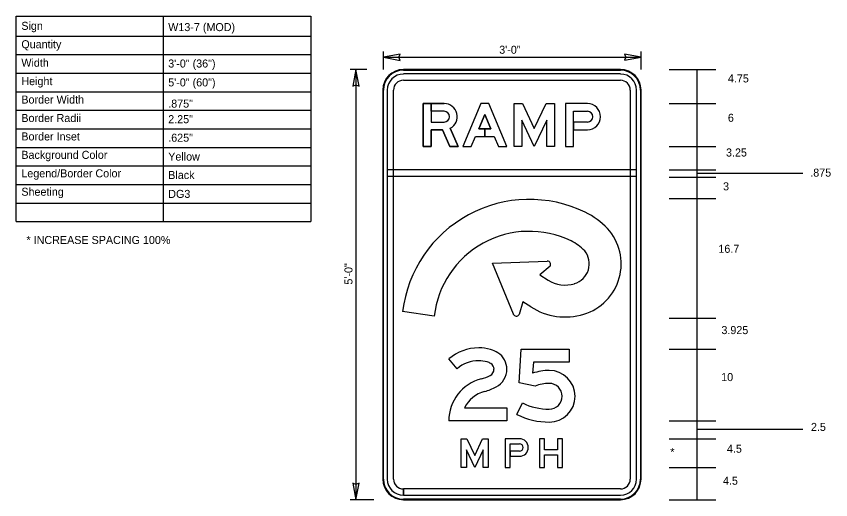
# Model space of a CAD drawing. Extents: x 582908 to 586041, y 1530940 to 1533040.
# Drawn here: x 583018 to 584437, y 1532197 to 1533040 of the extents above; entities that cross this region are included whole.
import ezdxf

# ---------------------------------------------------------------- set-up
doc = ezdxf.new("R2010")
doc.units = 0
for name, color, linetype in [('GSDims', 7, 'Continuous'), ('SheetLinesMisc2_dp', 7, 'Continuous'), ('SignPanel', 7, 'Continuous'), ('TextMisc', 7, 'Continuous'), ('TextNotes', 7, 'Continuous'), ('TextShtNo', 7, 'Continuous')]:
    doc.layers.add(name, color=color, linetype=linetype)

msp = doc.modelspace()

# ---------------------------------------------------------------- linework, layer by layer
at = {"layer": 'GSDims'}
for p, q in [((583657.9, 1532947), (583657.9, 1532978.4)), ((583686.9, 1532973.8), (583657.9, 1532968.4)), ((583657.9, 1532968.4), (584106.8, 1532968.4)), ((583657.9, 1532968.4), (583686.9, 1532962.8)), ((583684.7, 1532968.4), (583686.9, 1532973.8)), ((583686.9, 1532962.8), (583684.7, 1532968.4)), ((584106.8, 1532968.4), (584077.8, 1532974)), ((584077.8, 1532974), (584080, 1532968.4)), ((584080, 1532968.4), (584077.8, 1532963)), ((584077.8, 1532963), (584106.8, 1532968.4)), ((584106.8, 1532947), (584106.8, 1532978.4)), ((583629, 1532947), (583600, 1532947)), ((583610, 1532947), (583604.4, 1532918)), ((583610, 1532947), (583610, 1532197)), ((583615.4, 1532918), (583610, 1532947)), ((584155.6, 1532947), (584236.8, 1532947)), ((584204.3, 1532197), (584204.3, 1532947)), ((583604.4, 1532918), (583610, 1532920.2)), ((583610, 1532920.2), (583615.4, 1532918)), ((584155.6, 1532887.6), (584236.8, 1532887.6)), ((584155.6, 1532812.6), (584236.8, 1532812.6)), ((584155.6, 1532772), (584236.8, 1532772)), ((584155.6, 1532759.5), (584236.8, 1532759.5)), ((584204.3, 1532766.5), (584388.7, 1532766.5)), ((584155.6, 1532722), (584236.8, 1532722)), ((584155.6, 1532513.2), (584236.8, 1532513.2)), ((584155.6, 1532459.5), (584236.8, 1532459.5)), ((584155.6, 1532334.5), (584236.8, 1532334.5)), ((584204.3, 1532320.1), (584354, 1532320.1)), ((584343.4, 1532320.1), (584388.7, 1532320.1)), ((584155.6, 1532303.2), (584236.8, 1532303.2)), ((584155.6, 1532253.2), (584236.8, 1532253.2)), ((583610, 1532223.8), (583604.6, 1532226)), ((583604.6, 1532226), (583610, 1532197)), ((583610, 1532197), (583615.6, 1532226)), ((583615.6, 1532226), (583610, 1532223.8)), ((583641.4, 1532197), (583600, 1532197)), ((584155.6, 1532197), (584236.8, 1532197))]:
    msp.add_line(p, q, dxfattribs=at)
at = {"layer": 'SheetLinesMisc2_dp'}
for p, q in [((583018.3, 1532681.8), (583018.3, 1533039.8)), ((583018.3, 1533039.8), (583531.6, 1533039.8)), ((583274.2, 1533039.8), (583274.2, 1532681.8)), ((583531.6, 1533039.8), (583531.6, 1532681.8)), ((583018.3, 1533005.2), (583531.6, 1533005.2)), ((583018.3, 1532972.9), (583531.6, 1532972.9)), ((583018.3, 1532940.5), (583531.6, 1532940.5)), ((583018.3, 1532908.2), (583531.6, 1532908.2)), ((583018.3, 1532875.8), (583531.6, 1532875.8)), ((583018.3, 1532843.5), (583531.6, 1532843.5)), ((583018.3, 1532811.1), (583531.6, 1532811.1)), ((583018.3, 1532778.8), (583531.6, 1532778.8)), ((583018.3, 1532746.5), (583531.6, 1532746.5)), ((583018.3, 1532714.1), (583531.6, 1532714.1)), ((583018.3, 1532681.8), (583531.6, 1532681.8))]:
    msp.add_line(p, q, dxfattribs=at)
at = {"layer": 'SignPanel'}
for p, q in [((584070.9, 1532947), (583692.7, 1532947)), ((583692.7, 1532945.9), (584070.9, 1532945.9)), ((584070.9, 1532939.2), (583692.7, 1532939.2)), ((583692.7, 1532928.2), (584070.9, 1532928.2)), ((583656.8, 1532911), (583656.8, 1532232.9)), ((583657.9, 1532232.9), (583657.9, 1532911)), ((583664.6, 1532911), (583664.6, 1532232.9)), ((583675.6, 1532232.9), (583675.6, 1532911)), ((584088.1, 1532911), (584088.1, 1532232.9)), ((584099, 1532232.9), (584099, 1532911)), ((584105.7, 1532911), (584105.7, 1532232.9)), ((584106.8, 1532232.9), (584106.8, 1532911)), ((583988.9, 1532874.1), (584013.3, 1532874.1)), ((583988.9, 1532874.1), (584013.3, 1532874.1)), ((583988.9, 1532874.1), (584013.3, 1532874.1)), ((583988.9, 1532841.9), (584013.3, 1532841.9)), ((584099, 1532772), (583664.6, 1532772)), ((583664.6, 1532772), (583664.6, 1532761)), ((584099, 1532772), (583664.6, 1532772)), ((583664.6, 1532772), (583664.6, 1532761)), ((584099, 1532772), (583664.6, 1532772)), ((583664.6, 1532772), (583664.6, 1532761)), ((584099, 1532761), (584099, 1532772)), ((584099, 1532761), (584099, 1532772)), ((584099, 1532761), (584099, 1532772)), ((583664.6, 1532761), (584099, 1532761)), ((583664.6, 1532761), (584099, 1532761)), ((583664.6, 1532761), (584099, 1532761)), ((583847.9, 1532609.1), (583943.5, 1532613)), ((583884.3, 1532520.5), (583847.9, 1532609.1)), ((583948.3, 1532604.1), (583930.7, 1532589)), ((583930.7, 1532589), (583944.7, 1532580)), ((583900.7, 1532542.2), (583894.3, 1532519.9)), ((583914.7, 1532533.2), (583900.7, 1532542.2)), ((583746.4, 1532516.9), (583691.4, 1532525.3)), ((583890.5, 1532345.4), (583900.5, 1532365.6)), ((583890.5, 1532345.4), (583900.5, 1532365.6)), ((583890.5, 1532345.4), (583900.5, 1532365.6)), ((583878.9, 1532294.2), (583895.1, 1532294.2)), ((583878.9, 1532294.2), (583895.1, 1532294.2)), ((583878.9, 1532294.2), (583895.1, 1532294.2)), ((583878.9, 1532272.7), (583895.1, 1532272.7)), ((583692.7, 1532204.8), (583692.7, 1532215.7)), ((584070.9, 1532215.7), (583692.9, 1532215.7)), ((583692.9, 1532215.7), (583692.9, 1532204.8)), ((583692.9, 1532204.8), (584070.9, 1532204.8)), ((583692.7, 1532197), (583692.7, 1532198.1)), ((584070.9, 1532198.1), (583692.8, 1532198.1)), ((583692.8, 1532198.1), (583692.8, 1532197)), ((583692.8, 1532197), (584070.9, 1532197))]:
    msp.add_line(p, q, dxfattribs=at)
for points in [[(583763.7, 1532887.6), (583727.4, 1532887.6), (583727.4, 1532812.6), (583740.9, 1532812.6), (583740.9, 1532841.9), (583760.8, 1532841.9), (583773.5, 1532812.6), (583788.2, 1532812.6), (583774.4, 1532844.5)], [(583774.4, 1532844.5), (583788.2, 1532812.6), (583773.5, 1532812.6), (583760.8, 1532841.9), (583740.9, 1532841.9), (583740.9, 1532812.6), (583727.4, 1532812.6), (583727.4, 1532887.6), (583740.9, 1532887.6), (583740.9, 1532855.4), (583763.7, 1532855.4)], [(583774.4, 1532844.5), (583788.2, 1532812.6), (583773.5, 1532812.6), (583760.8, 1532841.9), (583740.9, 1532841.9), (583740.9, 1532812.6), (583727.4, 1532812.6), (583727.4, 1532887.6), (583740.9, 1532887.6), (583740.9, 1532855.4), (583763.7, 1532855.4)], [(583740.9, 1532874.1), (583740.9, 1532887.6), (583763.7, 1532887.6)], [(583740.9, 1532874.1), (583740.9, 1532887.6), (583763.7, 1532887.6)], [(584013.3, 1532887.6), (583975.4, 1532887.6), (583975.4, 1532812.6), (583988.9, 1532812.6), (583988.9, 1532841.9)], [(584013.3, 1532887.6), (583975.4, 1532887.6), (583975.4, 1532812.6), (583988.9, 1532812.6), (583988.9, 1532874.1)], [(584013.3, 1532887.6), (583975.4, 1532887.6), (583975.4, 1532812.6), (583988.9, 1532812.6), (583988.9, 1532874.1)], [(583763.7, 1532874.1), (583740.9, 1532874.1), (583740.9, 1532855.4), (583763.7, 1532855.4)], [(583763.7, 1532874.1), (583740.9, 1532874.1)], [(583763.7, 1532874.1), (583740.9, 1532874.1)], [(584013.3, 1532855.4), (583988.9, 1532855.4), (583988.9, 1532874.1)], [(584013.3, 1532855.4), (583988.9, 1532855.4), (583988.9, 1532841.9), (584013.3, 1532841.9)], [(584013.3, 1532855.4), (583988.9, 1532855.4), (583988.9, 1532841.9), (584013.3, 1532841.9)], [(583922.1, 1532395.1), (583894.3, 1532400.7), (583898, 1532459.5), (583981.8, 1532459.5), (583981.8, 1532437), (583919.2, 1532437), (583917.9, 1532417.5)], [(583922.1, 1532395.1), (583894.3, 1532400.7), (583898, 1532459.5), (583981.8, 1532459.5), (583981.8, 1532437), (583919.2, 1532437), (583917.9, 1532417.5)], [(583922.1, 1532395.1), (583894.3, 1532400.7), (583898, 1532459.5), (583981.8, 1532459.5), (583981.8, 1532437), (583919.2, 1532437), (583917.9, 1532417.5)], [(583786.4, 1532425.4), (583771.8, 1532442.5)], [(583786.4, 1532425.4), (583771.8, 1532442.5)], [(583786.4, 1532425.4), (583771.8, 1532442.5)], [(583799.3, 1532357), (583873, 1532357), (583873, 1532334.5), (583771.8, 1532334.5)], [(583799.3, 1532357), (583873, 1532357), (583873, 1532334.5), (583771.8, 1532334.5)], [(583799.3, 1532357), (583873, 1532357), (583873, 1532334.5), (583771.8, 1532334.5)], [(583895.1, 1532303.2), (583869.9, 1532303.2), (583869.9, 1532253.2), (583878.9, 1532253.2), (583878.9, 1532272.7)], [(583895.1, 1532303.2), (583869.9, 1532303.2), (583869.9, 1532253.2), (583878.9, 1532253.2), (583878.9, 1532294.2)], [(583895.1, 1532303.2), (583869.9, 1532303.2), (583869.9, 1532253.2), (583878.9, 1532253.2), (583878.9, 1532294.2)], [(583895.1, 1532281.7), (583878.9, 1532281.7), (583878.9, 1532294.2)], [(583895.1, 1532281.7), (583878.9, 1532281.7), (583878.9, 1532272.7), (583895.1, 1532272.7)], [(583895.1, 1532281.7), (583878.9, 1532281.7), (583878.9, 1532272.7), (583895.1, 1532272.7)]]:
    msp.add_lwpolyline(points, dxfattribs=at)
for points in [[(583818.4, 1532830.2), (583850.8, 1532830.2), (583858.2, 1532812.6), (583872.9, 1532812.6), (583841.4, 1532887.6), (583827.9, 1532887.6), (583796.4, 1532812.6), (583811, 1532812.6)], [(583845.2, 1532843.7), (583834.6, 1532843.7), (583834.6, 1532830.2), (583850.8, 1532830.2), (583858.2, 1532812.6), (583872.9, 1532812.6), (583841.4, 1532887.6), (583827.9, 1532887.6), (583796.4, 1532812.6), (583811, 1532812.6), (583818.4, 1532830.2), (583834.6, 1532830.2), (583834.6, 1532843.7), (583824.1, 1532843.7), (583834.6, 1532868.8)], [(583845.2, 1532843.7), (583834.6, 1532843.7), (583834.6, 1532830.2), (583850.8, 1532830.2), (583858.2, 1532812.6), (583872.9, 1532812.6), (583841.4, 1532887.6), (583827.9, 1532887.6), (583796.4, 1532812.6), (583811, 1532812.6), (583818.4, 1532830.2), (583834.6, 1532830.2), (583834.6, 1532843.7), (583824.1, 1532843.7), (583834.6, 1532868.8)], [(583920.8, 1532844.1), (583941.5, 1532887.6), (583956, 1532887.6), (583956, 1532812.6), (583942.5, 1532812.6), (583942.5, 1532858.4), (583920.8, 1532812.6), (583899, 1532858.4), (583899, 1532812.6), (583885.5, 1532812.6), (583885.5, 1532887.6), (583900.1, 1532887.6)], [(583920.8, 1532844.1), (583941.5, 1532887.6), (583956, 1532887.6), (583956, 1532812.6), (583942.5, 1532812.6), (583942.5, 1532858.4), (583920.8, 1532812.6), (583899, 1532858.4), (583899, 1532812.6), (583885.5, 1532812.6), (583885.5, 1532887.6), (583900.1, 1532887.6)], [(583920.8, 1532844.1), (583941.5, 1532887.6), (583956, 1532887.6), (583956, 1532812.6), (583942.5, 1532812.6), (583942.5, 1532858.4), (583920.8, 1532812.6), (583899, 1532858.4), (583899, 1532812.6), (583885.5, 1532812.6), (583885.5, 1532887.6), (583900.1, 1532887.6)], [(583845.2, 1532843.7), (583834.6, 1532868.8), (583824.1, 1532843.7)], [(583817, 1532274.2), (583830.8, 1532303.2), (583840.5, 1532303.2), (583840.5, 1532253.2), (583831.5, 1532253.2), (583831.5, 1532283.7), (583817, 1532253.2), (583802.5, 1532283.7), (583802.5, 1532253.2), (583793.5, 1532253.2), (583793.5, 1532303.2), (583803.2, 1532303.2)], [(583817, 1532274.2), (583830.8, 1532303.2), (583840.5, 1532303.2), (583840.5, 1532253.2), (583831.5, 1532253.2), (583831.5, 1532283.7), (583817, 1532253.2), (583802.5, 1532283.7), (583802.5, 1532253.2), (583793.5, 1532253.2), (583793.5, 1532303.2), (583803.2, 1532303.2)], [(583817, 1532274.2), (583830.8, 1532303.2), (583840.5, 1532303.2), (583840.5, 1532253.2), (583831.5, 1532253.2), (583831.5, 1532283.7), (583817, 1532253.2), (583802.5, 1532283.7), (583802.5, 1532253.2), (583793.5, 1532253.2), (583793.5, 1532303.2), (583803.2, 1532303.2)], [(583961.1, 1532284.2), (583938.6, 1532284.2), (583938.6, 1532303.2), (583929.6, 1532303.2), (583929.6, 1532253.2), (583938.6, 1532253.2), (583938.6, 1532275.2), (583961.1, 1532275.2), (583961.1, 1532253.2), (583970.1, 1532253.2), (583970.1, 1532303.2), (583961.1, 1532303.2)], [(583961.1, 1532284.2), (583938.6, 1532284.2), (583938.6, 1532303.2), (583929.6, 1532303.2), (583929.6, 1532253.2), (583938.6, 1532253.2), (583938.6, 1532275.2), (583961.1, 1532275.2), (583961.1, 1532253.2), (583970.1, 1532253.2), (583970.1, 1532303.2), (583961.1, 1532303.2)], [(583961.1, 1532284.2), (583938.6, 1532284.2), (583938.6, 1532303.2), (583929.6, 1532303.2), (583929.6, 1532253.2), (583938.6, 1532253.2), (583938.6, 1532275.2), (583961.1, 1532275.2), (583961.1, 1532253.2), (583970.1, 1532253.2), (583970.1, 1532303.2), (583961.1, 1532303.2)]]:
    msp.add_lwpolyline(points, close=True, dxfattribs=at)
for centre, radius, start, end in [((583692.7, 1532911), 35.9, 90, 180), ((583692.7, 1532911), 34.8, 90, 180), ((583692.7, 1532911), 28.1, 90, 180), ((584070.9, 1532911), 35.9, 0, 90), ((584070.9, 1532911), 34.8, 0, 90), ((584070.9, 1532911), 28.1, 0, 90), ((583692.7, 1532911), 17.2, 90, 180), ((584070.9, 1532911), 17.2, 0, 90), ((583912.1, 1532498.2), 222.3, 64.0026, 173.0199), ((583945.4, 1532569.1), 144.1, 44.3092, 63.5547), ((583980.5, 1532608.2), 91.7, 286.8096, 42.1395), ((583912.1, 1532498.2), 166.7, 64.0026, 173.5767), ((583945.4, 1532569.1), 88.4, 44.3092, 63.5547), ((583980.5, 1532608.2), 36.1, 286.8096, 38.803), ((583943.7, 1532607.4), 5.6, 324.4393, 92.3246), ((583974.7, 1532626.8), 55.6, 237.3246, 286.8677), ((583974.7, 1532626.8), 111.2, 237.3246, 286.8677), ((583889.4, 1532522.6), 5.56, 202.3246, 331.1534), ((583692.7, 1532232.9), 35.9, 180, 270), ((583692.7, 1532232.9), 34.8, 180, 270), ((583692.7, 1532232.9), 28.1, 180, 270), ((583692.7, 1532232.9), 17.2, 180, 270), ((584070.9, 1532232.9), 28.1, 270, 0), ((584070.9, 1532232.9), 17.2, 270, 0), ((584070.9, 1532232.9), 35.9, 270, 0), ((584070.9, 1532232.9), 34.8, 270, 0)]:
    msp.add_arc(centre, radius, start, end, dxfattribs=at)
for centre, major_axis, start_param, end_param in [((583763.7, 1532864.7), (0, 22.9), 3.62744, 6.283185), ((583763.7, 1532864.7), (0, 22.9), 3.62744, 6.283185), ((583763.7, 1532864.7), (0, 22.9), 3.62744, 6.283185), ((584013.3, 1532864.7), (0, 22.9), 3.141593, 6.283185), ((584013.3, 1532864.7), (0, 22.9), 3.141593, 6.283185), ((584013.3, 1532864.7), (0, 22.9), 3.141593, 6.283185), ((583763.7, 1532864.7), (0, 9.37), 3.141593, 6.283185), ((583763.7, 1532864.7), (0, 9.37), 3.141593, 6.283185), ((583763.7, 1532864.7), (0, 9.37), 3.141593, 6.283185), ((584013.3, 1532864.7), (0, 9.37), 3.141593, 6.283185), ((584013.3, 1532864.7), (0, 9.37), 3.141593, 6.283185), ((584013.3, 1532864.7), (0, 9.37), 3.141593, 6.283185), ((583824, 1532381), (0, 80.7), 0, 0.70376), ((583824, 1532381), (0, 80.7), 0, 0.70376), ((583824, 1532381), (0, 80.7), 0, 0.70376), ((583824, 1532382.7), (0, 79), 6.02311, 6.283185), ((583824, 1532382.7), (0, 79), 6.02311, 6.283185), ((583824, 1532382.7), (0, 79), 6.02311, 6.283185), ((583832.5, 1532414.7), (0, 45.8), 5.706931, 6.02311), ((583832.5, 1532414.7), (0, 45.8), 5.706931, 6.02311), ((583832.5, 1532414.7), (0, 45.8), 5.706931, 6.02311), ((583838.9, 1532424.5), (0, 34.2), 4.712389, 5.706931), ((583838.9, 1532424.5), (0, 34.2), 4.712389, 5.706931), ((583838.9, 1532424.5), (0, 34.2), 4.712389, 5.706931), ((583824, 1532381), (0, 58.2), 0, 0.70376), ((583824, 1532381), (0, 58.2), 0, 0.70376), ((583824, 1532381), (0, 58.2), 0, 0.70376), ((583824, 1532382.7), (0, 56.5), 6.02311, 6.283185), ((583824, 1532382.7), (0, 56.5), 6.02311, 6.283185), ((583824, 1532382.7), (0, 56.5), 6.02311, 6.283185), ((583832.5, 1532414.7), (0, 23.3), 5.706931, 6.02311), ((583832.5, 1532414.7), (0, 23.3), 5.706931, 6.02311), ((583832.5, 1532414.7), (0, 23.3), 5.706931, 6.02311), ((583838.9, 1532424.5), (0, 11.7), 4.712389, 5.706931), ((583838.9, 1532424.5), (0, 11.7), 4.712389, 5.706931), ((583838.9, 1532424.5), (0, 11.7), 4.712389, 5.706931), ((583838.1, 1532424.5), (0, 12.4), 3.626327, 4.712389), ((583838.1, 1532424.5), (0, 12.4), 3.626327, 4.712389), ((583838.1, 1532424.5), (0, 12.4), 3.626327, 4.712389), ((583838.1, 1532424.5), (0, 34.9), 3.626327, 4.712389), ((583838.1, 1532424.5), (0, 34.9), 3.626327, 4.712389), ((583838.1, 1532424.5), (0, 34.9), 3.626327, 4.712389), ((583946.8, 1532332.3), (0, 90), 0, 0.326688), ((583946.8, 1532332.3), (0, 90), 0, 0.326688), ((583946.8, 1532332.3), (0, 90), 0, 0.326688), ((583946.8, 1532377.3), (0, 45), 3.141593, 6.283185), ((583946.8, 1532377.3), (0, 45), 3.141593, 6.283185), ((583946.8, 1532377.3), (0, 45), 3.141593, 6.283185), ((583847.3, 1532334.5), (0, 75.5), 0.25053, 1.570796), ((583847.3, 1532334.5), (0, 75.5), 0.25053, 1.570796), ((583847.3, 1532334.5), (0, 75.5), 0.25053, 1.570796), ((583811.1, 1532475.8), (0, 70.4), 3.392123, 3.626327), ((583811.1, 1532475.8), (0, 70.4), 3.392123, 3.626327), ((583811.1, 1532475.8), (0, 70.4), 3.392123, 3.626327), ((583946.8, 1532332.3), (0, 67.5), 0, 0.374869), ((583946.8, 1532332.3), (0, 67.5), 0, 0.374869), ((583946.8, 1532332.3), (0, 67.5), 0, 0.374869), ((583946.8, 1532377.3), (0, 22.5), 3.141593, 6.283185), ((583946.8, 1532377.3), (0, 22.5), 3.141593, 6.283185), ((583946.8, 1532377.3), (0, 22.5), 3.141593, 6.283185), ((583847.3, 1532334.5), (0, 53), 0.25053, 1.132058), ((583847.3, 1532334.5), (0, 53), 0.25053, 1.132058), ((583847.3, 1532334.5), (0, 53), 0.25053, 1.132058), ((583811.1, 1532475.8), (0, 92.9), 3.392123, 3.626327), ((583811.1, 1532475.8), (0, 92.9), 3.392123, 3.626327), ((583811.1, 1532475.8), (0, 92.9), 3.392123, 3.626327), ((583946.8, 1532459.2), (0, 104.4), 2.68226, 3.141593), ((583946.8, 1532459.2), (0, 104.4), 2.68226, 3.141593), ((583946.8, 1532459.2), (0, 104.4), 2.68226, 3.141593), ((583946.8, 1532459.2), (0, 126.9), 2.68226, 3.141593), ((583946.8, 1532459.2), (0, 126.9), 2.68226, 3.141593), ((583946.8, 1532459.2), (0, 126.9), 2.68226, 3.141593), ((583895.1, 1532288), (0, 15.2), 3.141593, 6.283185), ((583895.1, 1532288), (0, 15.2), 3.141593, 6.283185), ((583895.1, 1532288), (0, 15.2), 3.141593, 6.283185), ((583895.1, 1532288), (0, 6.25), 3.141593, 6.283185), ((583895.1, 1532288), (0, 6.25), 3.141593, 6.283185), ((583895.1, 1532288), (0, 6.25), 3.141593, 6.283185)]:
    msp.add_ellipse(centre, major_axis=major_axis, ratio=0.999998, start_param=start_param, end_param=end_param, dxfattribs=at)

# ---------------------------------------------------------------- texts
at = {"layer": 'GSDims'}
for s, p in [('3\'-0"', (583859.7, 1532974.4)), ('4.75', (584258.1, 1532924.4)), ('6', (584258.1, 1532855.8)), ('3.25', (584254.8, 1532795.3)), ('.875', (584401.6, 1532760.2)), ('3', (584249.7, 1532736.3)), ('16.7', (584241.5, 1532627.4)), ('3.925', (584246.8, 1532485.7)), ('10', (584246.4, 1532403.8)), ('2.5', (584402.8, 1532316.9)), ('*', (584157.7, 1532273.2)), ('4.5', (584256.4, 1532278.9)), ('4.5', (584249.5, 1532223.1))]:
    msp.add_text(s, height=14, dxfattribs=at).set_placement(p)
msp.add_text('5\'-0"', height=14, rotation=90, dxfattribs=at).set_placement((583604, 1532572))
at = {"layer": 'TextMisc'}
for s, p in [('Sign', (583027.1, 1533016.1)), ('Quantity', (583027.1, 1532984)), ('Width', (583027.1, 1532951.8)), ('Height', (583027.1, 1532919.7)), ('Border Width', (583027.1, 1532887.6)), ('Border Radii', (583027.1, 1532855.4)), ('Border Inset', (583027.1, 1532823.3)), ('Background Color', (583027.1, 1532791.2)), ('Legend/Border Color', (583027.1, 1532759)), ('Sheeting', (583027.1, 1532726.9))]:
    msp.add_text(s, height=14, dxfattribs=at).set_placement(p)
at = {"layer": 'TextNotes'}
msp.add_text('* INCREASE SPACING 100%', height=14, dxfattribs=at).set_placement((583036.1, 1532642.8))
at = {"layer": 'TextShtNo'}
for s, p in [('W13-7 (MOD)', (583283, 1533013.9)), ('3\'-0" (36")', (583283, 1532950.4)), ('5\'-0" (60")', (583283, 1532917.5)), ('.875"', (583283, 1532880.5)), ('2.25"', (583283, 1532853.4)), ('.625"', (583283, 1532821.1)), ('Yellow', (583283, 1532788.2)), ('Black', (583283, 1532756.1)), ('DG3', (583283, 1532723.1))]:
    msp.add_text(s, height=14, dxfattribs=at).set_placement(p)

doc.saveas('drawing.dxf')
